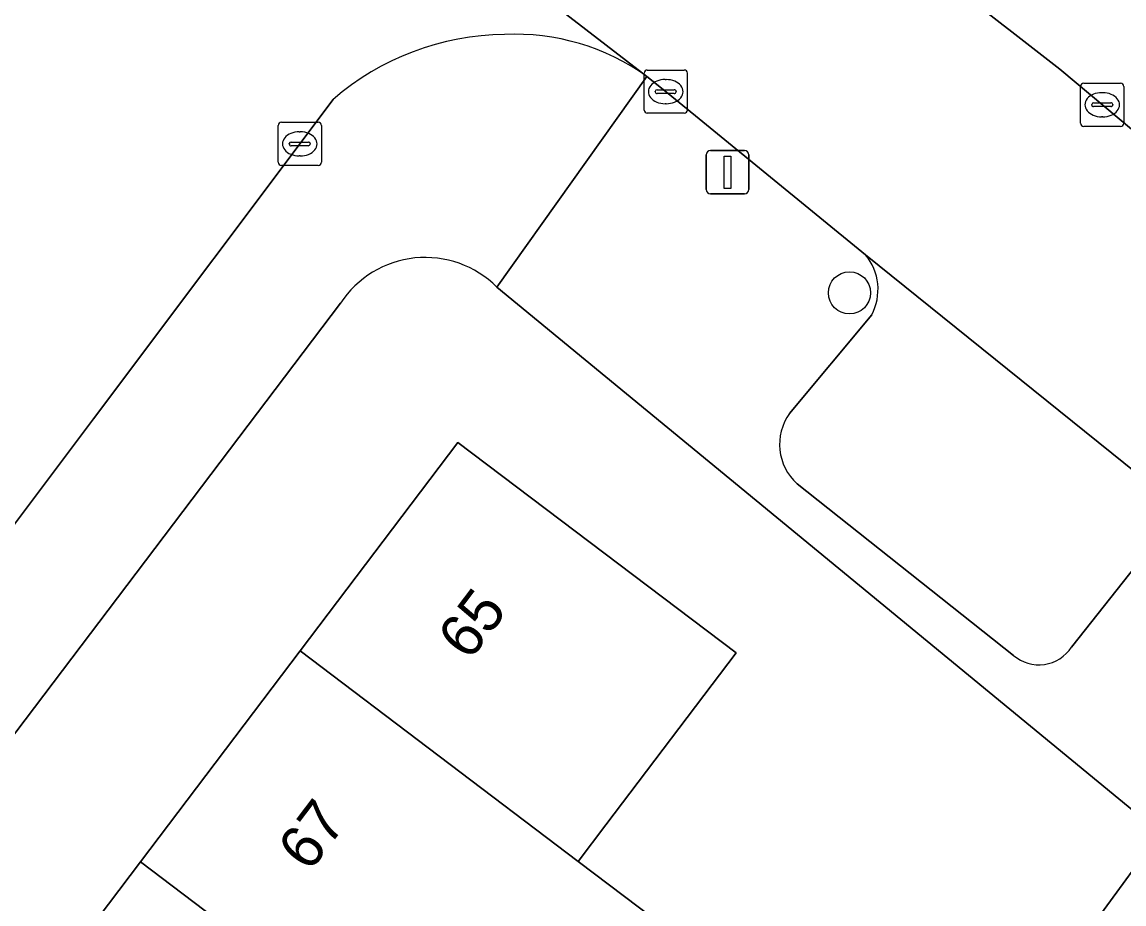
# Model space of a CAD drawing. Extents: x 159039 to 160102, y 381214 to 382524.
# Drawn here: x 159414.31 to 159439.83, y 381979.8 to 382000.22 of the extents above; entities that cross this region are included whole.
import ezdxf

# ---------------------------------------------------------------- set-up
doc = ezdxf.new("R2010")
doc.units = 0
for name, color, linetype in [('IMGEO_Boom', 7, 'Continuous'), ('IMGEO_Erf', 7, 'Continuous'), ('IMGEO_Kolk', 7, 'Continuous'), ('IMGEO_Lichtmast', 7, 'Continuous'), ('IMGEO_Pand', 7, 'Continuous'), ('IMGEO_Pand_nummerreeks', 7, 'Continuous'), ('IMGEO_Parkeervlak_open', 7, 'Continuous'), ('IMGEO_Rijbaan_lokaal_open', 7, 'Continuous'), ('IMGEO_Voetpad_open', 7, 'Continuous')]:
    doc.layers.add(name, color=color, linetype=linetype)

msp = doc.modelspace()

# ---------------------------------------------------------------- linework, layer by layer
at = {"layer": 'IMGEO_Boom'}
msp.add_circle((159433.47, 381993.953), 0.489, dxfattribs=at)
at = {"layer": 'IMGEO_Erf'}
for points in [[(159430.883, 381973.082), (159433.242, 381976.199), (159435.584, 381979.292), (159437.843, 381977.581), (159439.221, 381979.469), (159440.661, 381981.451), (159425.306, 381994.084)], [(159421.683, 381993.713), (159398.906, 381963.628), (159402.187, 381961.144), (159405.915, 381966.068), (159409.669, 381971.027), (159413.342, 381975.878), (159417.049, 381980.775), (159420.747, 381985.661), (159424.404, 381990.491), (159430.843, 381985.616), (159427.826, 381981.63), (159427.186, 381980.785), (159429.997, 381978.658), (159426.299, 381973.772), (159423.488, 381975.899), (159419.78, 381971.003), (159422.368, 381969.043), (159420.853, 381967.042), (159418.265, 381969.001), (159416.107, 381966.151), (159412.354, 381961.193), (159408.626, 381956.269), (159416.944, 381949.973)]]:
    msp.add_lwpolyline(points, dxfattribs=at)
msp.add_arc((159423.645, 381992.427), 2.346, 44.9253, 146.7683, dxfattribs=at)
at = {"layer": 'IMGEO_Kolk'}
for p, q in [((159428.714, 381998.187), (159428.714, 381999.039)), ((159428.789, 381999.113), (159429.641, 381999.113)), ((159429.715, 381999.039), (159429.715, 381998.187)), ((159429.202, 381998.893), (159429.227, 381998.893)), ((159438.897, 381998.809), (159439.749, 381998.809)), ((159428.973, 381998.607), (159428.973, 381998.619)), ((159429.411, 381998.57), (159429.013, 381998.57)), ((159429.016, 381998.656), (159429.414, 381998.656)), ((159429.457, 381998.619), (159429.457, 381998.607)), ((159438.822, 381997.883), (159438.822, 381998.735)), ((159439.31, 381998.589), (159439.335, 381998.589)), ((159439.823, 381998.735), (159439.823, 381997.883)), ((159429.225, 381998.333), (159429.2, 381998.333)), ((159439.081, 381998.303), (159439.081, 381998.315)), ((159439.519, 381998.266), (159439.121, 381998.266)), ((159439.124, 381998.352), (159439.522, 381998.352)), ((159439.565, 381998.315), (159439.565, 381998.303)), ((159429.641, 381998.113), (159428.789, 381998.113)), ((159439.333, 381998.029), (159439.308, 381998.029)), ((159420.24, 381996.977), (159420.24, 381997.829)), ((159420.315, 381997.903), (159421.167, 381997.903)), ((159421.241, 381997.829), (159421.241, 381996.977)), ((159439.749, 381997.809), (159438.897, 381997.809)), ((159420.728, 381997.683), (159420.753, 381997.683)), ((159420.499, 381997.397), (159420.499, 381997.409)), ((159420.937, 381997.36), (159420.539, 381997.36)), ((159420.542, 381997.446), (159420.94, 381997.446)), ((159420.983, 381997.409), (159420.983, 381997.397)), ((159420.751, 381997.123), (159420.726, 381997.123)), ((159421.167, 381996.903), (159420.315, 381996.903))]:
    msp.add_line(p, q, dxfattribs=at)
for points in [[(159428.714, 381998.187), (159428.714, 381999.039)], [(159428.789, 381999.113), (159429.641, 381999.113)], [(159429.715, 381999.039), (159429.715, 381998.187)], [(159438.897, 381998.809), (159439.749, 381998.809)], [(159438.822, 381997.883), (159438.822, 381998.735)], [(159439.823, 381998.735), (159439.823, 381997.883)], [(159429.641, 381998.113), (159428.789, 381998.113)], [(159420.24, 381996.977), (159420.24, 381997.829)], [(159420.315, 381997.903), (159421.167, 381997.903)], [(159421.241, 381997.829), (159421.241, 381996.977)], [(159439.749, 381997.809), (159438.897, 381997.809)], [(159421.167, 381996.903), (159420.315, 381996.903)]]:
    msp.add_lwpolyline(points, dxfattribs=at)
for centre, radius, start, end in [((159428.791, 381999.037), 0.0765, 91.552, 178.448), ((159428.791, 381999.037), 0.0765, 91.552, 178.448), ((159429.639, 381999.037), 0.0765, 1.552, 88.448), ((159429.639, 381999.037), 0.0765, 1.552, 88.448), ((159438.899, 381998.733), 0.0765, 91.552, 178.448), ((159438.899, 381998.733), 0.0765, 91.552, 178.448), ((159439.747, 381998.733), 0.0765, 1.552, 88.448), ((159439.747, 381998.733), 0.0765, 1.552, 88.448), ((159429.013, 381998.616), 0.0403, 85.8775, 175.7526), ((159429.01, 381998.606), 0.0366, 178.938, 274.7102), ((159429.414, 381998.613), 0.043, 264.8664, 352.4533), ((159429.418, 381998.618), 0.0386, 1.7309, 96.639), ((159439.121, 381998.312), 0.0403, 85.8775, 175.7526), ((159439.118, 381998.302), 0.0366, 178.938, 274.7102), ((159439.522, 381998.309), 0.043, 264.8664, 352.4533), ((159439.526, 381998.314), 0.0386, 1.7309, 96.639), ((159428.791, 381998.189), 0.0765, 181.552, 268.448), ((159428.791, 381998.189), 0.0765, 181.552, 268.448), ((159429.639, 381998.189), 0.0765, 271.552, 358.448), ((159429.639, 381998.189), 0.0765, 271.552, 358.448), ((159420.317, 381997.827), 0.0765, 91.552, 178.448), ((159420.317, 381997.827), 0.0765, 91.552, 178.448), ((159421.165, 381997.827), 0.0765, 1.552, 88.448), ((159421.165, 381997.827), 0.0765, 1.552, 88.448), ((159438.899, 381997.885), 0.0765, 181.552, 268.448), ((159438.899, 381997.885), 0.0765, 181.552, 268.448), ((159439.747, 381997.885), 0.0765, 271.552, 358.448), ((159439.747, 381997.885), 0.0765, 271.552, 358.448), ((159420.539, 381997.406), 0.0403, 85.8775, 175.7526), ((159420.536, 381997.396), 0.0366, 178.938, 274.7102), ((159420.94, 381997.403), 0.043, 264.8664, 352.4533), ((159420.944, 381997.408), 0.0386, 1.7309, 96.639), ((159420.317, 381996.979), 0.0765, 181.552, 268.448), ((159420.317, 381996.979), 0.0765, 181.552, 268.448), ((159421.165, 381996.979), 0.0765, 271.552, 358.448), ((159421.165, 381996.979), 0.0765, 271.552, 358.448)]:
    msp.add_arc(centre, radius, start, end, dxfattribs=at)
for centre, major_axis, ratio, start_param, end_param in [((159429.201, 381998.613), (-0.387, 0.002), 0.722429, 4.712389, 7.853982), ((159429.226, 381998.613), (-0.39, 0.002), 0.717154, 1.570796, 4.712389), ((159439.309, 381998.309), (-0.387, 0.002), 0.722429, 4.712389, 7.853982), ((159439.334, 381998.309), (-0.39, 0.002), 0.717154, 1.570796, 4.712389), ((159420.727, 381997.403), (-0.387, 0.002), 0.722429, 4.712389, 7.853982), ((159420.752, 381997.403), (-0.39, 0.002), 0.717154, 1.570796, 4.712389)]:
    msp.add_ellipse(centre, major_axis=major_axis, ratio=ratio, start_param=start_param, end_param=end_param, dxfattribs=at)
at = {"layer": 'IMGEO_Lichtmast'}
for p, q in [((159430.25, 381997.247), (159431.04, 381997.247)), ((159431.04, 381997.247), (159430.25, 381997.247)), ((159430.15, 381996.347), (159430.15, 381997.147)), ((159430.15, 381997.147), (159430.15, 381996.347)), ((159431.14, 381997.147), (159431.14, 381996.347)), ((159431.14, 381996.347), (159431.14, 381997.147)), ((159431.04, 381996.247), (159430.25, 381996.247)), ((159430.25, 381996.247), (159431.04, 381996.247))]:
    msp.add_line(p, q, dxfattribs=at)
msp.add_lwpolyline([(159430.57, 381997.122), (159430.72, 381997.122), (159430.72, 381996.372), (159430.57, 381996.372), (159430.57, 381997.122)], dxfattribs=at)
for centre, start, end in [((159430.25, 381997.147), 90, 180), ((159430.25, 381997.147), 90, 180), ((159431.04, 381997.147), 0, 90), ((159431.04, 381997.147), 360, 90), ((159430.25, 381996.347), 180, 270), ((159430.25, 381996.347), 180, 270), ((159431.04, 381996.347), 270, 0), ((159431.04, 381996.347), 270, 0)]:
    msp.add_arc(centre, 0.1, start, end, dxfattribs=at)
at = {"layer": 'IMGEO_Pand'}
for points in [[(159420.747, 381985.661), (159427.186, 381980.785), (159427.826, 381981.63), (159430.843, 381985.616), (159424.404, 381990.491)], [(159420.747, 381985.661), (159417.049, 381980.775), (159423.488, 381975.899), (159426.299, 381973.772), (159429.997, 381978.658), (159427.186, 381980.785)], [(159413.342, 381975.878), (159419.78, 381971.003), (159423.488, 381975.899), (159417.049, 381980.775)]]:
    msp.add_lwpolyline(points, close=True, dxfattribs=at)
at = {"layer": 'IMGEO_Parkeervlak_open'}
for points in [[(159441.923, 381988.326), (159433.841, 381994.834)], [(159433.984, 381993.443), (159432.084, 381991.162)], [(159432.257, 381989.532), (159437.269, 381985.558)], [(159438.61, 381985.751), (159440.552, 381988.192)]]:
    msp.add_lwpolyline(points, dxfattribs=at)
for centre, radius, start, end in [((159432.875, 381994.032), 1.256, 332.0445, 39.6947), ((159433.081, 381990.444), 1.229, 144.2246, 227.8922), ((159437.856, 381986.234), 0.896, 229.0498, 327.33)]:
    msp.add_arc(centre, radius, start, end, dxfattribs=at)
at = {"layer": 'IMGEO_Rijbaan_lokaal_open'}
for points in [[(159403.117, 382018.417), (159413.97, 382010.442), (159414.131, 382010.342), (159414.649, 382009.857), (159428.781, 381998.963), (159429.268, 381998.566), (159433.841, 381994.834), (159441.923, 381988.326)], [(159445.068, 381993.5), (159438.342, 381999.131), (159437.228, 382000), (159436.96, 382000.209), (159433.343, 382003.032), (159431.111, 382004.883), (159430.938, 382005.027), (159428.686, 382006.888), (159423.484, 382011.193)], [(159428.781, 381998.963), (159414.649, 382009.857), (159415.443, 382009.112)], [(159416.185, 382003.138), (159413.774, 382000), (159413.438, 381999.563), (159413.105, 381999.127), (159408.558, 381993.176), (159406.641, 381990.648), (159412.416, 381986.311), (159415.967, 381991.036), (159421.514, 381998.432)]]:
    msp.add_lwpolyline(points, dxfattribs=at)
for centre, radius, start, end in [((159425.537, 381993.795), 6.139, 90.5085, 130.948), ((159425.745, 381994.737), 5.203, 54.3029, 92.886)]:
    msp.add_arc(centre, radius, start, end, dxfattribs=at)
at = {"layer": 'IMGEO_Voetpad_open'}
for points in [[(159418.213, 382015.458), (159418.831, 382015.025), (159423.484, 382011.193), (159428.686, 382006.888), (159430.938, 382005.027), (159431.111, 382004.883), (159433.343, 382003.032), (159436.96, 382000.209), (159437.228, 382000), (159438.342, 381999.131), (159445.068, 381993.5), (159453.588, 381986.5), (159465.366, 381976.894), (159470.716, 381972.439), (159478.439, 381966.173), (159490.011, 381956.729), (159493.902, 381953.566), (159495.4, 381952.384)], [(159425.306, 381994.084), (159428.781, 381998.963)], [(159433.841, 381994.834), (159429.268, 381998.566), (159428.781, 381998.963), (159425.306, 381994.084), (159440.661, 381981.451), (159439.221, 381979.469), (159440.673, 381978.378), (159444.624, 381983.484), (159447.671, 381981.125), (159443.753, 381976.064), (159444.955, 381975.01), (159445.658, 381975.93), (159448.827, 381980.123), (159461.871, 381969.531), (159473.165, 381960.187), (159474.224, 381959.31), (159482.645, 381952.343), (159486.209, 381949.671), (159490.205, 381946.373), (159490.624, 381945.41), (159490.602, 381944.349), (159490.312, 381943.7), (159492.043, 381946.011)], [(159421.514, 381998.432), (159415.967, 381991.036), (159412.416, 381986.311), (159410.86, 381984.24), (159405.257, 381976.785), (159392.08, 381959.597), (159382.82, 381947.331), (159375.274, 381937.448), (159369.627, 381929.935), (159365.099, 381923.996), (159363.697, 381922.105), (159362.178, 381920.056), (159360.046, 381917.18), (159356.505, 381912.787)], [(159358.765, 381910.606), (159381.864, 381941.117), (159382.726, 381942.256), (159397.868, 381962.257), (159398.906, 381963.628), (159421.683, 381993.713)], [(159432.084, 381991.162), (159433.984, 381993.443)], [(159437.269, 381985.558), (159432.257, 381989.532)], [(159440.552, 381988.192), (159438.61, 381985.751)]]:
    msp.add_lwpolyline(points, dxfattribs=at)
for centre, radius, start, end in [((159425.537, 381993.795), 6.139, 90.5085, 130.948), ((159425.745, 381994.737), 5.203, 54.3029, 92.886), ((159423.645, 381992.427), 2.346, 44.9253, 146.7683), ((159432.875, 381994.032), 1.256, 332.0445, 39.6947), ((159433.081, 381990.444), 1.229, 144.2246, 227.8922), ((159437.856, 381986.234), 0.896, 229.0498, 327.33)]:
    msp.add_arc(centre, radius, start, end, dxfattribs=at)

# ---------------------------------------------------------------- texts
at = {"layer": 'IMGEO_Pand_nummerreeks'}
for s, rotation, p in [('65', 52.8726, (159424.669, 381985.407)), ('67', 52.8725, (159420.966, 381980.516))]:
    msp.add_text(s, height=1, rotation=rotation, dxfattribs=at).set_placement(p)

doc.saveas('drawing.dxf')
